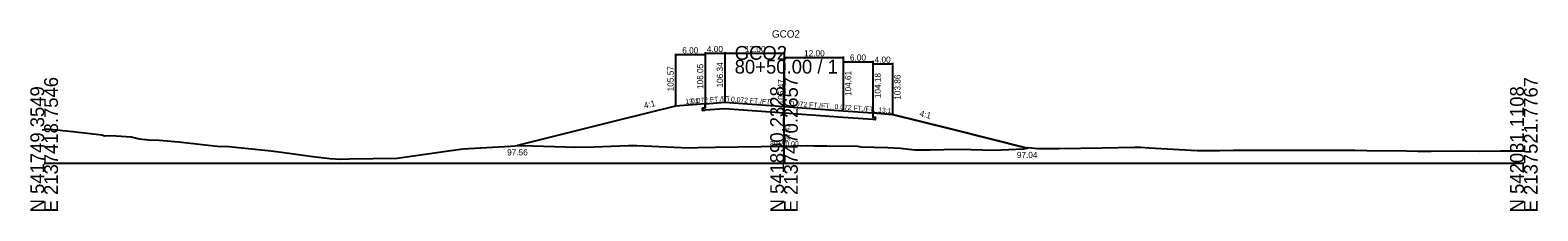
# Model space of a CAD drawing. Extents: x -14327 to 8886, y -10 to 39048.
# Drawn here: x 2997.2 to 3302.8, y 20990.3 to 21027 of the extents above; entities that cross this region are included whole.
import ezdxf

# ---------------------------------------------------------------- set-up
doc = ezdxf.new("R2010")
doc.units = 0
for name, color, linetype in [('Level 5', 7, 'Continuous'), ('Level 53', 7, 'Continuous'), ('Level 54', 7, 'Continuous'), ('Level 55', 7, 'Continuous'), ('Level 7', 7, 'Continuous'), ('RD_GPK_XS_Cell', 7, 'Continuous'), ('RD_XS_EwShp', 7, 'Continuous'), ('RD_XS_ExGround', 7, 'Continuous'), ('RD_XS_Pave', 7, 'Continuous'), ('RD_XS_TX_Baseline', 7, 'Continuous'), ('RD_XS_TX_Elev_EX', 7, 'Continuous'), ('RD_XS_TX_Elev_PR', 7, 'Continuous'), ('RD_XS_TX_Station', 7, 'Continuous')]:
    doc.layers.add(name, color=color, linetype=linetype)

msp = doc.modelspace()

# ---------------------------------------------------------------- linework, layer by layer
at = {"layer": 'Level 5'}
for p, q in [((3134, 21011.22), (3133.5, 21011.18)), ((3133.5, 21011.18), (3133.5, 21010.68)), ((3133.5, 21010.68), (3134, 21010.72)), ((3134, 21012.05), (3134, 21011.22)), ((3138, 21011.01), (3134, 21010.72)), ((3150, 21010.14), (3138, 21011.01)), ((3162, 21009.28), (3150, 21010.14)), ((3168, 21010.18), (3168, 21009.35)), ((3168, 21008.85), (3162, 21009.28)), ((3168, 21009.35), (3168.5, 21009.31)), ((3168.5, 21008.81), (3168, 21008.85)), ((3168.5, 21009.31), (3168.5, 21008.81))]:
    msp.add_line(p, q, dxfattribs=at)
at = {"layer": 'Level 54'}
for p, q in [((3128, 21022.2), (3128, 21011.77)), ((3134, 21022), (3128, 21022)), ((3134, 21022.49), (3134, 21012.25)), ((3134, 21022.29), (3138, 21022.29)), ((3134, 21022.2), (3134, 21012.25)), ((3138, 21022.49), (3138, 21012.54)), ((3138, 21022.29), (3150, 21022.29)), ((3150, 21022.49), (3150, 21011.67)), ((3150, 21021.62), (3150, 21011.67)), ((3150, 21021.42), (3162, 21021.42)), ((3162, 21021.62), (3162, 21010.81)), ((3162, 21020.76), (3162, 21010.81)), ((3162, 21020.56), (3168, 21020.56)), ((3168, 21020.76), (3168, 21010.38)), ((3168, 21020.33), (3168, 21010.38)), ((3168, 21020.13), (3172, 21020.13)), ((3172, 21020.33), (3172, 21010.06))]:
    msp.add_line(p, q, dxfattribs=at)
at = {"layer": 'Level 7'}
for p, q in [((3128, 21011.57), (3116, 21008.57)), ((3134, 21012.05), (3128, 21011.57)), ((3168, 21010.18), (3172, 21009.86)), ((3172, 21009.86), (3184, 21006.86)), ((3116, 21008.57), (3095.96, 21003.56)), ((3184, 21006.86), (3199.29, 21003.04))]:
    msp.add_line(p, q, dxfattribs=at)
at = {"layer": 'RD_GPK_XS_Cell'}
for p, q in [((3150, 21000), (3150, 21020.97)), ((3000, 21000), (3150, 21000)), ((3150, 21000), (3300, 21000))]:
    msp.add_line(p, q, dxfattribs=at)
at = {"layer": 'RD_XS_EwShp'}
msp.add_lwpolyline([(3168, 21010.18), (3168, 21009.35), (3168.5, 21009.31), (3168.5, 21008.81), (3168, 21008.85), (3162, 21009.28), (3150, 21010.14), (3138, 21011.01), (3134, 21010.72), (3133.5, 21010.68), (3133.5, 21011.18), (3134, 21011.22), (3134, 21012.05), (3128, 21011.57), (3116, 21008.57), (3095.96, 21003.56), (3096.35, 21003.59), (3096.89, 21003.56), (3107.81, 21003.27), (3111.47, 21003.29), (3118.49, 21003.61), (3119.26, 21003.61), (3120.15, 21003.59), (3130.71, 21003.12), (3132.55, 21003.16), (3136.06, 21003.24), (3150, 21003.47), (3154.78, 21003.55), (3156.04, 21003.48), (3158.66, 21003.5), (3164.95, 21003.41), (3165.53, 21003.32), (3171.04, 21003.14), (3173.64, 21003.01), (3175.31, 21002.82), (3176.53, 21002.67), (3179.62, 21002.7), (3185.15, 21002.83), (3187.98, 21002.76), (3192.55, 21002.63), (3198.62, 21002.91), (3199.29, 21003.04), (3184, 21006.86), (3172, 21009.86)], close=True, dxfattribs=at)
at = {"layer": 'RD_XS_ExGround'}
for p, q in [((3000, 21006.99), (3001.14, 21006.91)), ((3001.14, 21006.91), (3005.82, 21006.41)), ((3005.82, 21006.41), (3011.67, 21005.75)), ((3011.67, 21005.75), (3012.24, 21005.54)), ((3012.24, 21005.54), (3013.6, 21005.61)), ((3013.6, 21005.61), (3017.61, 21005.34)), ((3017.61, 21005.34), (3019.23, 21004.96)), ((3019.23, 21004.96), (3021.15, 21004.7)), ((3021.15, 21004.7), (3023.29, 21004.69)), ((3023.29, 21004.69), (3027.23, 21004.35)), ((3027.23, 21004.35), (3035.71, 21003.39)), ((3035.71, 21003.39), (3036.75, 21003.42)), ((3036.75, 21003.42), (3045.4, 21002.54)), ((3084.9, 21002.88), (3094.52, 21003.46)), ((3094.52, 21003.46), (3096.35, 21003.59)), ((3096.35, 21003.59), (3096.89, 21003.56)), ((3096.89, 21003.56), (3107.81, 21003.27)), ((3111.47, 21003.29), (3118.49, 21003.61)), ((3118.49, 21003.61), (3119.26, 21003.61)), ((3119.26, 21003.61), (3120.15, 21003.59)), ((3120.15, 21003.59), (3130.71, 21003.12)), ((3136.06, 21003.24), (3150, 21003.47)), ((3150, 21003.47), (3154.78, 21003.55)), ((3154.78, 21003.55), (3156.04, 21003.48)), ((3156.04, 21003.48), (3158.66, 21003.5)), ((3158.66, 21003.5), (3164.95, 21003.41)), ((3164.95, 21003.41), (3165.53, 21003.32)), ((3045.4, 21002.54), (3046.57, 21002.45)), ((3046.57, 21002.45), (3047.1, 21002.38)), ((3047.1, 21002.38), (3048.14, 21002.24)), ((3048.14, 21002.24), (3054.5, 21001.35)), ((3054.5, 21001.35), (3057.93, 21000.97)), ((3057.93, 21000.97), (3060.16, 21000.8)), ((3060.16, 21000.8), (3061.86, 21000.84)), ((3061.86, 21000.84), (3071.58, 21001)), ((3071.58, 21001), (3080.55, 21002.31)), ((3080.55, 21002.31), (3084.9, 21002.88)), ((3107.81, 21003.27), (3111.47, 21003.29)), ((3130.71, 21003.12), (3132.55, 21003.16)), ((3132.55, 21003.16), (3136.06, 21003.24)), ((3165.53, 21003.32), (3171.04, 21003.14)), ((3171.04, 21003.14), (3173.64, 21003.01)), ((3173.64, 21003.01), (3175.31, 21002.82)), ((3175.31, 21002.82), (3176.53, 21002.67)), ((3176.53, 21002.67), (3179.62, 21002.7)), ((3179.62, 21002.7), (3185.15, 21002.83)), ((3185.15, 21002.83), (3187.98, 21002.76)), ((3187.98, 21002.76), (3192.55, 21002.63)), ((3192.55, 21002.63), (3198.62, 21002.91)), ((3198.62, 21002.91), (3199.34, 21003.04)), ((3199.34, 21003.04), (3199.55, 21003.17)), ((3199.55, 21003.17), (3201.4, 21002.98)), ((3201.4, 21002.98), (3202.63, 21002.94)), ((3202.63, 21002.94), (3205.81, 21002.99)), ((3205.81, 21002.99), (3214.51, 21003.12)), ((3214.51, 21003.12), (3221.04, 21003.22)), ((3221.04, 21003.22), (3222.34, 21003.22)), ((3222.34, 21003.22), (3224.06, 21003.13)), ((3224.06, 21003.13), (3233.8, 21002.59)), ((3233.8, 21002.59), (3238.36, 21002.56)), ((3238.36, 21002.56), (3241.11, 21002.63)), ((3241.11, 21002.63), (3251.41, 21002.6)), ((3251.41, 21002.6), (3265.72, 21002.63)), ((3265.72, 21002.63), (3268.16, 21002.58)), ((3268.16, 21002.58), (3276.24, 21002.5)), ((3276.24, 21002.5), (3278.51, 21002.45)), ((3278.51, 21002.45), (3278.84, 21002.46)), ((3278.84, 21002.46), (3281.18, 21002.46)), ((3281.18, 21002.46), (3286.56, 21002.47)), ((3286.56, 21002.47), (3291.06, 21002.45)), ((3291.06, 21002.45), (3295.35, 21002.51)), ((3295.35, 21002.51), (3300, 21002.51))]:
    msp.add_line(p, q, dxfattribs=at)
at = {"layer": 'RD_XS_Pave'}
for p, q in [((3134, 21012.05), (3138, 21012.34)), ((3138, 21012.34), (3150, 21011.47)), ((3150, 21011.47), (3162, 21010.61)), ((3162, 21010.61), (3168, 21010.18))]:
    msp.add_line(p, q, dxfattribs=at)

# ---------------------------------------------------------------- texts
at = {"layer": 'Level 53'}
for s, rotation, p in [('105.57', 90, (3127.62, 21014.57)), ('106.05', 90, (3133.62, 21015.05)), ('106.34', 90, (3137.62, 21015.34)), ('104.61', 90, (3163.62, 21013.61)), ('104.18', 90, (3169.62, 21013.18)), ('103.86', 90, (3173.62, 21012.86)), ('4:1', 14.0362, (3121.76, 21011.04)), ('4:1', 345.9638, (3177.39, 21009.54))]:
    msp.add_text(s, height=1.25, rotation=rotation, dxfattribs=at).set_placement(p)
for s, p in [('97.56', (3093.86, 21001.56)), ('97.04', (3197.21, 21001.04))]:
    msp.add_text(s, height=1.25, dxfattribs=at).set_placement(p)
at = {"layer": 'Level 54'}
for s, p in [('6.00', (3129.37, 21022.25)), ('4.00', (3134.37, 21022.54)), ('12.00', (3142.07, 21022.54)), ('12.00', (3154.07, 21021.67)), ('6.00', (3163.37, 21020.81)), ('4.00', (3168.37, 21020.38))]:
    msp.add_text(s, height=1.25, dxfattribs=at).set_placement(p)
at = {"layer": 'Level 55'}
for s, rotation, p in [('13:1', 4.5739, (3130.03, 21011.98)), ('0.072 FT./FT.', 4.1182, (3131.18, 21012.1)), ('0.072 FT./FT.', 355.8818, (3139.22, 21012.5)), ('0.072 FT./FT.', 355.8818, (3151.22, 21011.64)), ('0.072 FT./FT.', 355.8818, (3160.22, 21010.99)), ('13:1', 355.4261, (3169.07, 21010.34))]:
    msp.add_text(s, height=1, rotation=rotation, dxfattribs=at).set_placement(p)
at = {"layer": 'RD_GPK_XS_Cell'}
for s, p in [('GCO2', (3140, 21020.97)), ('80+50.00 / 1', (3140, 21018.17))]:
    msp.add_text(s, height=2.8, dxfattribs=at).set_placement(p)
for s, p in [('E 2137418.7546', (3002.8, 20990)), ('E 2137470.2657', (3152.8, 20990)), ('E 2137521.7767', (3302.8, 20990)), ('N 541749.3549', (3000, 20990)), ('N 541890.2328', (3150, 20990)), ('N 542031.1108', (3300, 20990))]:
    msp.add_text(s, height=2.8, rotation=90, dxfattribs=at).set_placement(p)
at = {"layer": 'RD_XS_TX_Baseline'}
msp.add_text('GCO2', height=1.5, dxfattribs=at).set_placement((3147.55, 21025.47))
at = {"layer": 'RD_XS_TX_Elev_EX'}
msp.add_text('97.47', height=1, rotation=90, dxfattribs=at).set_placement((3151.25, 21004.47))
at = {"layer": 'RD_XS_TX_Elev_PR'}
msp.add_text(' 105.47', height=1.25, rotation=90, dxfattribs=at).set_placement((3150, 21011.47))
at = {"layer": 'RD_XS_TX_Station'}
msp.add_text('80+50.00', height=1, dxfattribs=at).set_placement((3147.18, 21003.47))

doc.saveas('drawing.dxf')
